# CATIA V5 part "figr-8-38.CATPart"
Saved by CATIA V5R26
Part number: Part2
Bounding box of the stored display mesh (mm): x -50 to 50, y -50 to 50, z 0 to 40
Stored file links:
  D:\_Deepak\CATIA\CATIA V5-6R2016_Deepak\Resources\Part files\Partfiles\c08_catia_v5_6r2016_prt\figr-8-38.CATPart
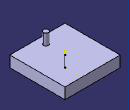
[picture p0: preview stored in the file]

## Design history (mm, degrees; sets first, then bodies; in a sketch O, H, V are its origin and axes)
Body1 (main body)
  Sketch1 on xy-plane, origin (0, 0, 0), H (1, 0, 0), V (0, 1, 0)
    line L1 (-50, 50) -> (50, 50)
    line L2 (50, 50) -> (50, -50)
    line L3 (50, -50) -> (-50, -50)
    line L4 (-50, -50) -> (-50, 50)
    axis line L5 (50, -50) -> (-50, 50)
    length L2 = 100
    length L3 = 100
    horizontal: L1 H, L3 H
    vertical: L2 V, L4 V
    midpoint: O L5
  Pad1: profile Sketch1, direction (0, 0, 1), length 20
  Sketch2 on face of Pad1, origin (0, 0, 20), H (1, 0, 0), V (0, 1, 0)
    circle A1 centre (0, -34.6458) radius 4.7511
    point P1 (0, -34.6458)
    coincidence: P1 V
  Pad2: profile Sketch2, direction (0, 0, 1), length 20
  Sketch3 on yz-plane, origin (0, 0, 0), H (0, 1, 0), V (0, 0, 1)
    line L1 (0, 0) -> (0, 20.0386)
    vertical: L1 V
